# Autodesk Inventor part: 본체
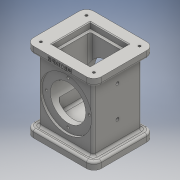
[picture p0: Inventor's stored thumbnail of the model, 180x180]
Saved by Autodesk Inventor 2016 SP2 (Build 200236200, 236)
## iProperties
Created: 2017-08
Part Number: 본체
Material: Generic
Document SubType Name: Modeling
Designer: Administrator
Density: 1 g/cm^3
Appearance: Default
Author: Administrator
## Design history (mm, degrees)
sketch "스케치1"
  geometry: L1 (-46, -41)-(46, -41); L2 (46, -41)-(46, 41); L3 (46, 41)-(-46, 41); L4 (-46, 41)-(-46, -41); L5 (-46, -41)-(46, 41); L6 (46, -41)-(-46, 41); 1 further point
  constraints: 12 end point, 2 midpoint, 2 parallel, 1 horizontal, 1 perpendicular
  dimensions: "d0" = 92 distance of L2.end L3.end; "d1" = 82 distance of L1.end L2.end
extrude "돌출1" new body sketch "스케치1" distance "d2" = 10; taper "d3" = 0 deg
fillet "모깎기1" dims "d4" = 10
sketch "스케치2"
  geometry: L1 (-37, -33)-(37, -33); L2 (37, -33)-(37, 33); L3 (37, 33)-(-37, 33); L4 (-37, 33)-(-37, -33); L5 (-37, -33)-(37, 33); L6 (37, -33)-(-37, 33); 1 further point
  constraints: 12 end point, 2 midpoint, 2 parallel, 1 horizontal, 1 perpendicular
  dimensions: "d5" = 74 distance of L3.end L2.end; "d6" = 66 distance of L2.end L1.end
extrude "돌출2" join sketch "스케치2" distance "d7" = 88; taper "d8" = 0 deg
sketch "스케치3"
  geometry: L1 (-46, -41)-(46, -41); L2 (46, -41)-(46, 41); L3 (46, 41)-(-46, 41); L4 (-46, 41)-(-46, -41); L5 (-46, -41)-(46, 41); L6 (46, -41)-(-46, 41); 1 further point
  constraints: 12 end point, 2 midpoint, 2 parallel, 1 horizontal, 1 perpendicular
  dimensions: "d9" = 92 distance of L3.end L2.end; "d10" = 82 distance of L2.end L1.end
extrude "돌출3" join sketch "스케치3" distance "d11" = 10; taper "d12" = 0 deg
fillet "모깎기2" dims "d13" = 10
fillet "모깎기3" dims "d14" = 3
fillet "모깎기4" dims "d15" = 3
sketch "스케치4"
  geometry: L1 (-26, -26)-(26, -26); L2 (26, -26)-(26, 26); L3 (26, 26)-(-26, 26); L4 (-26, 26)-(-26, -26); L5 (-26, -26)-(26, 26); L6 (26, -26)-(-26, 26); 1 further point
  constraints: 12 end point, 2 midpoint, 2 parallel, 1 horizontal, 1 perpendicular
  dimensions: "d16" = 52 distance of L3.end L2.end; "d17" = 52 distance of L2.end L1.end
extrude "돌출4" cut sketch "스케치4" distance "d18" = 8; taper "d19" = 0 deg
sketch "스케치5"
  geometry: L1 (24, 24)-(-24, 24); L2 (-24, 24)-(-24, -24); L3 (-24, -24)-(24, -24); L4 (24, -24)-(24, 24); L5 (24, 24)-(-24, -24); L6 (-24, 24)-(24, -24); 1 further point
  constraints: 12 end point, 2 midpoint, 2 parallel, 1 horizontal, 1 perpendicular
  dimensions: "d20" = 48 distance of L3.end L2.end; "d21" = 48 distance of L1.end L2.end
extrude "돌출5" cut sketch "스케치5" distance "d22" = 16; taper "d23" = 0 deg
sketch "스케치6"
  geometry: L1 (-22, -22)-(22, -22); L2 (22, -22)-(22, 22); L3 (22, 22)-(-22, 22); L4 (-22, 22)-(-22, -22); L5 (-22, -22)-(22, 22); L6 (22, -22)-(-22, 22); 1 further point
  constraints: 12 end point, 2 midpoint, 2 parallel, 1 horizontal, 1 perpendicular
  dimensions: "d24" = 44 distance of L3.end L2.end; "d25" = 44 distance of L2.end L1.end
extrude "돌출6" cut sketch "스케치6" distance "d26" = 74; taper "d27" = 0 deg
sketch "스케치7"
  geometry: C1 r 35 at (34, -41); 1 further point
  constraints: 1 centre point, 1 vertical alignment
  dimensions: "d28" = 70 diameter of C1; "d29" = 54 distance of point (34, -95) C1.centre
extrude "돌출7" cut sketch "스케치7" distance "d30" = 3; taper "d31" = 0 deg
fillet "모깎기5" dims "d69" = 3
fillet "모깎기6" dims "d70" = 3
fillet "모깎기7" dims "d71" = 3
sketch "스케치8"
  geometry: C1 r 35 at (0, 0) reference; C2 r 24 at (0, 0); 1 further point
  constraints: 1 centre point, 1 coincident
  dimensions: "d32" = 48 diameter of C2
extrude "돌출8" cut sketch "스케치8" stored distance "d33" = 3; taper "d34" = 0 deg
sketch "스케치9"
  geometry: L1 (95, -1)-(95, 61) reference; 4 further points
  constraints: 2 horizontal alignment, 1 midpoint
  dimensions: "d35" = 38 distance from line of point (57, 30) L1; "d36" = 42 distance of point (15, 30) point (57, 30)
hole "구멍1" sketch "스케치9" at (57, 30), (15, 30) diameter "d37" = 4.134; stored, may be unused: countersink angle "d41" = 90 deg, drill point angle "d43" = 118 deg; dims "d38" = 20, "d39" = 4, "d40" = 2, "d42" = 20
sketch "스케치10"
  geometry: L1 (0, 0)-(0, 29); A1 r 24 centre (0, 0) between (-19, -14.663) and (19, -14.663) reference; 4 further points
  constraints: 2 end point, 1 coincident, 1 vertical
  dimensions: "d44" = 29 distance of L1.start L1.end
hole "구멍2" sketch "스케치10" at (0, 29) diameter "d45" = 3.242; stored, may be unused: countersink angle "d49" = 90 deg, drill point angle "d51" = 118 deg; dims "d46" = 4, "d47" = 4, "d48" = 2, "d50" = 6
sketch "스케치11"
  geometry: A1 r 10 centre (-36, 31) between (-36, 41) and (-46, 31) reference; A2 r 10 centre (36, 31) between (46, 31) and (36, 41) reference; A3 r 10 centre (36, -31) between (36, -41) and (46, -31) reference; A4 r 10 centre (-36, -31) between (-46, -31) and (-36, -41) reference; 5 further points
  constraints: 4 coincident
hole "구멍3" sketch "스케치11" at (-36, 31), (36, 31), (36, -31), (-36, -31) diameter "d55" = 3.242; stored, may be unused: countersink angle "d59" = 90 deg, drill point angle "d61" = 118 deg; dims "d56" = 4, "d57" = 4, "d58" = 2, "d60" = 6
sketch "스케치12" dims "d13" = 10
  geometry: C1 r 1.621 at (36, -31) reference; A1 r 10 centre (-36, -31) between (-46, -31) and (-36, -41) reference; A2 r 10 centre (-36, 31) between (-36, 41) and (-46, 31) reference; A3 r 10 centre (36, 31) between (46, 31) and (36, 41) reference; 5 further points
  constraints: 4 coincident
hole "구멍4" sketch "스케치12" at (36, -31), (-36, -31), (-36, 31), (36, 31) diameter "d62" = 3.242; stored, may be unused: countersink angle "d66" = 90 deg, drill point angle "d68" = 118 deg; dims "d13" = 10, "d63" = 4, "d64" = 4, "d65" = 2, "d67" = 6
chamfer "모따기1" distance "d72" = 1; stored, may be unused: second distance "d73" = 2, angle "d74" = 45 deg
sketch "스케치13"
  geometry: L1 (-10, 0)-(-10, -7) reference; L2 (0, 0)-(72, 0) reference; 2 further points
  constraints: 1 other
  dimensions: "d75" = 46 distance from line of L1 point (36, -4); "d76" = 4 distance from line of L2 point (36, -4)
feature "엠보싱1" sketch "스케치13" dims "d0" = 92, "d1" = 82, "d77" = 0.5, "d78" = 0
node "솔리드1"
mirror "대칭1"
pattern_circular "원형 패턴1" dims angle "d53" = 360 deg
mirror "대칭2"
